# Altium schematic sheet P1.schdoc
size 594 x 419 mm; Symbol: Drawing-Symbol_A4; @Project Name: Inverted_MAML_6x6; @Page Count: 1; @Update Date: 2026-07-20; @Create Date: 2026-07-20; @Schematic Name: Schematic1; @Page No: 1; @Page Name: P1; Company: EasyEDA.com; Version: V1.0; Page Size: A4; Device: Drawing-Symbol_A4; @Create Time: 12:18:09; @Update Time: 12:18:09; Border: 1; Width: 2338; Height: 1652; Region Start: 1; X Region Count: 6; Y Region Count: 4; Blade Width: 10; Title Block Position: 3
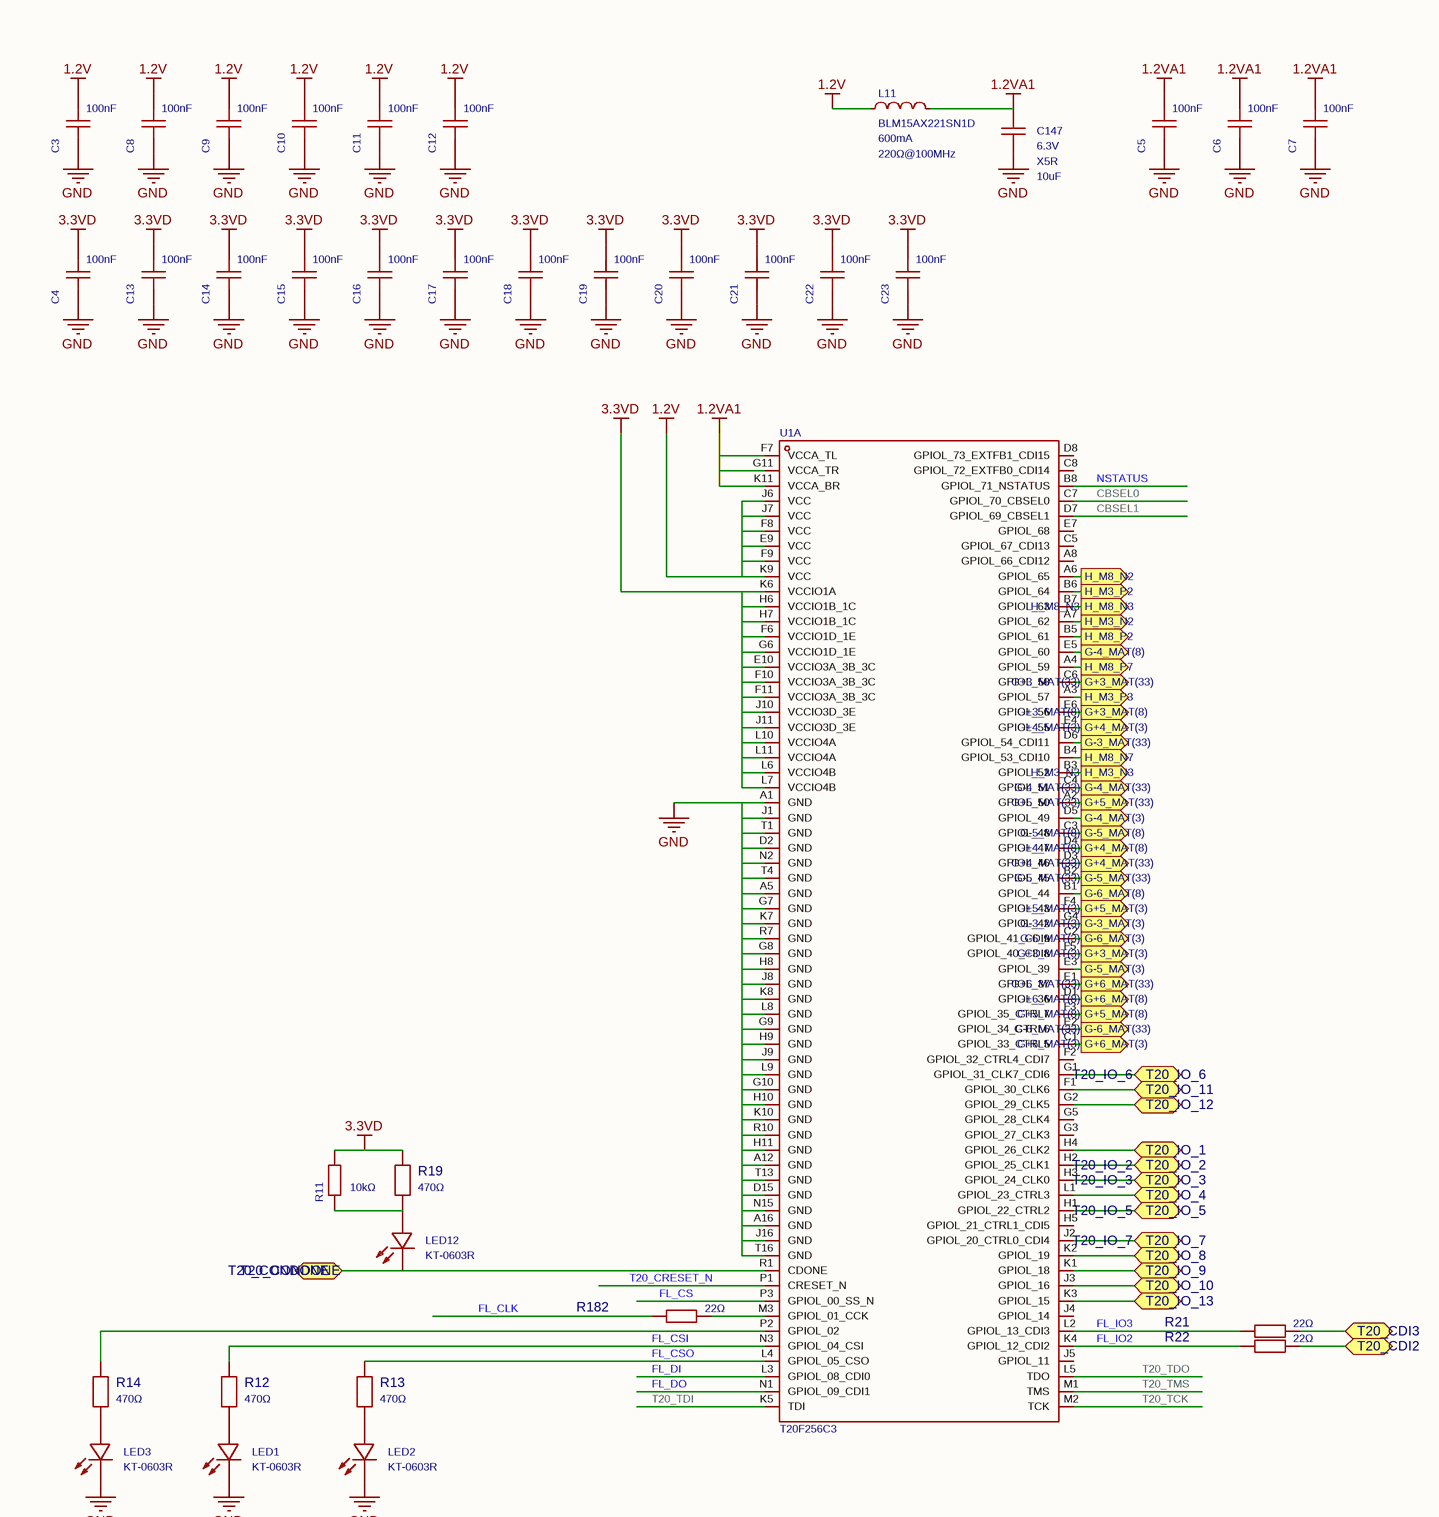
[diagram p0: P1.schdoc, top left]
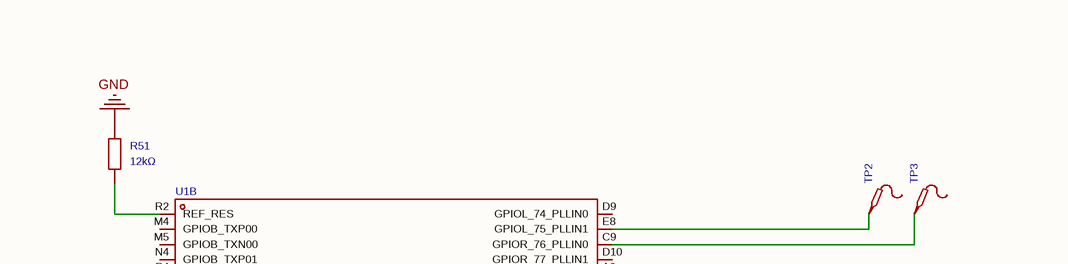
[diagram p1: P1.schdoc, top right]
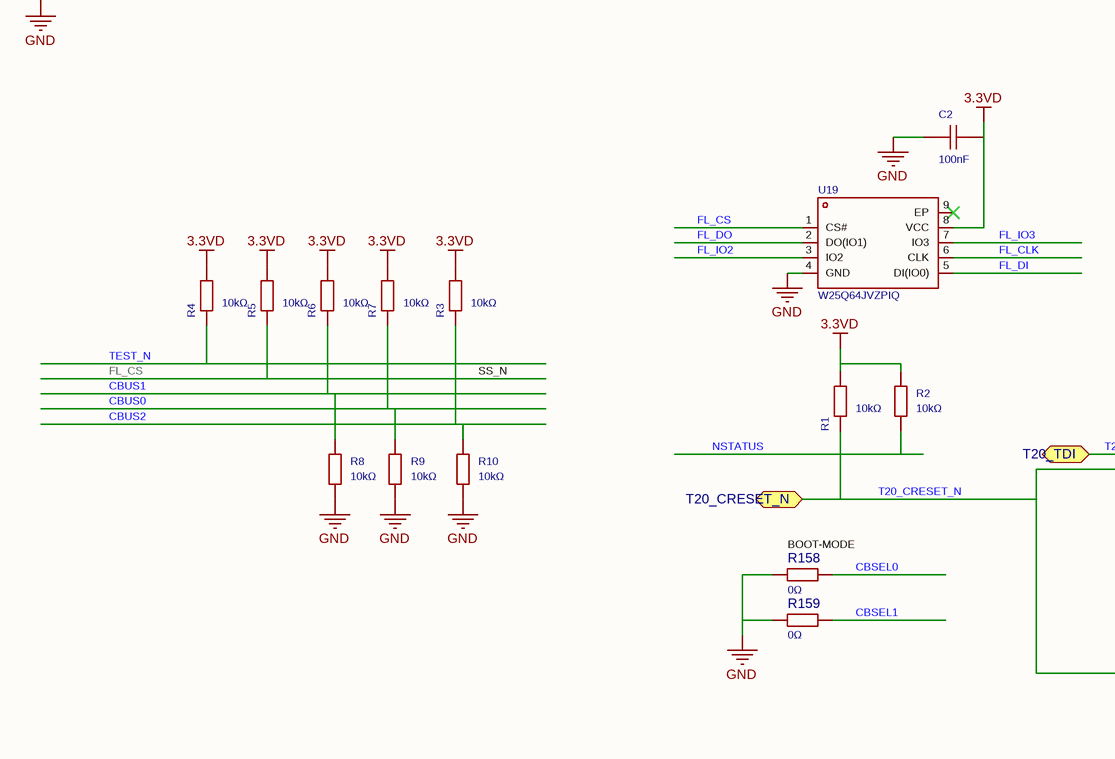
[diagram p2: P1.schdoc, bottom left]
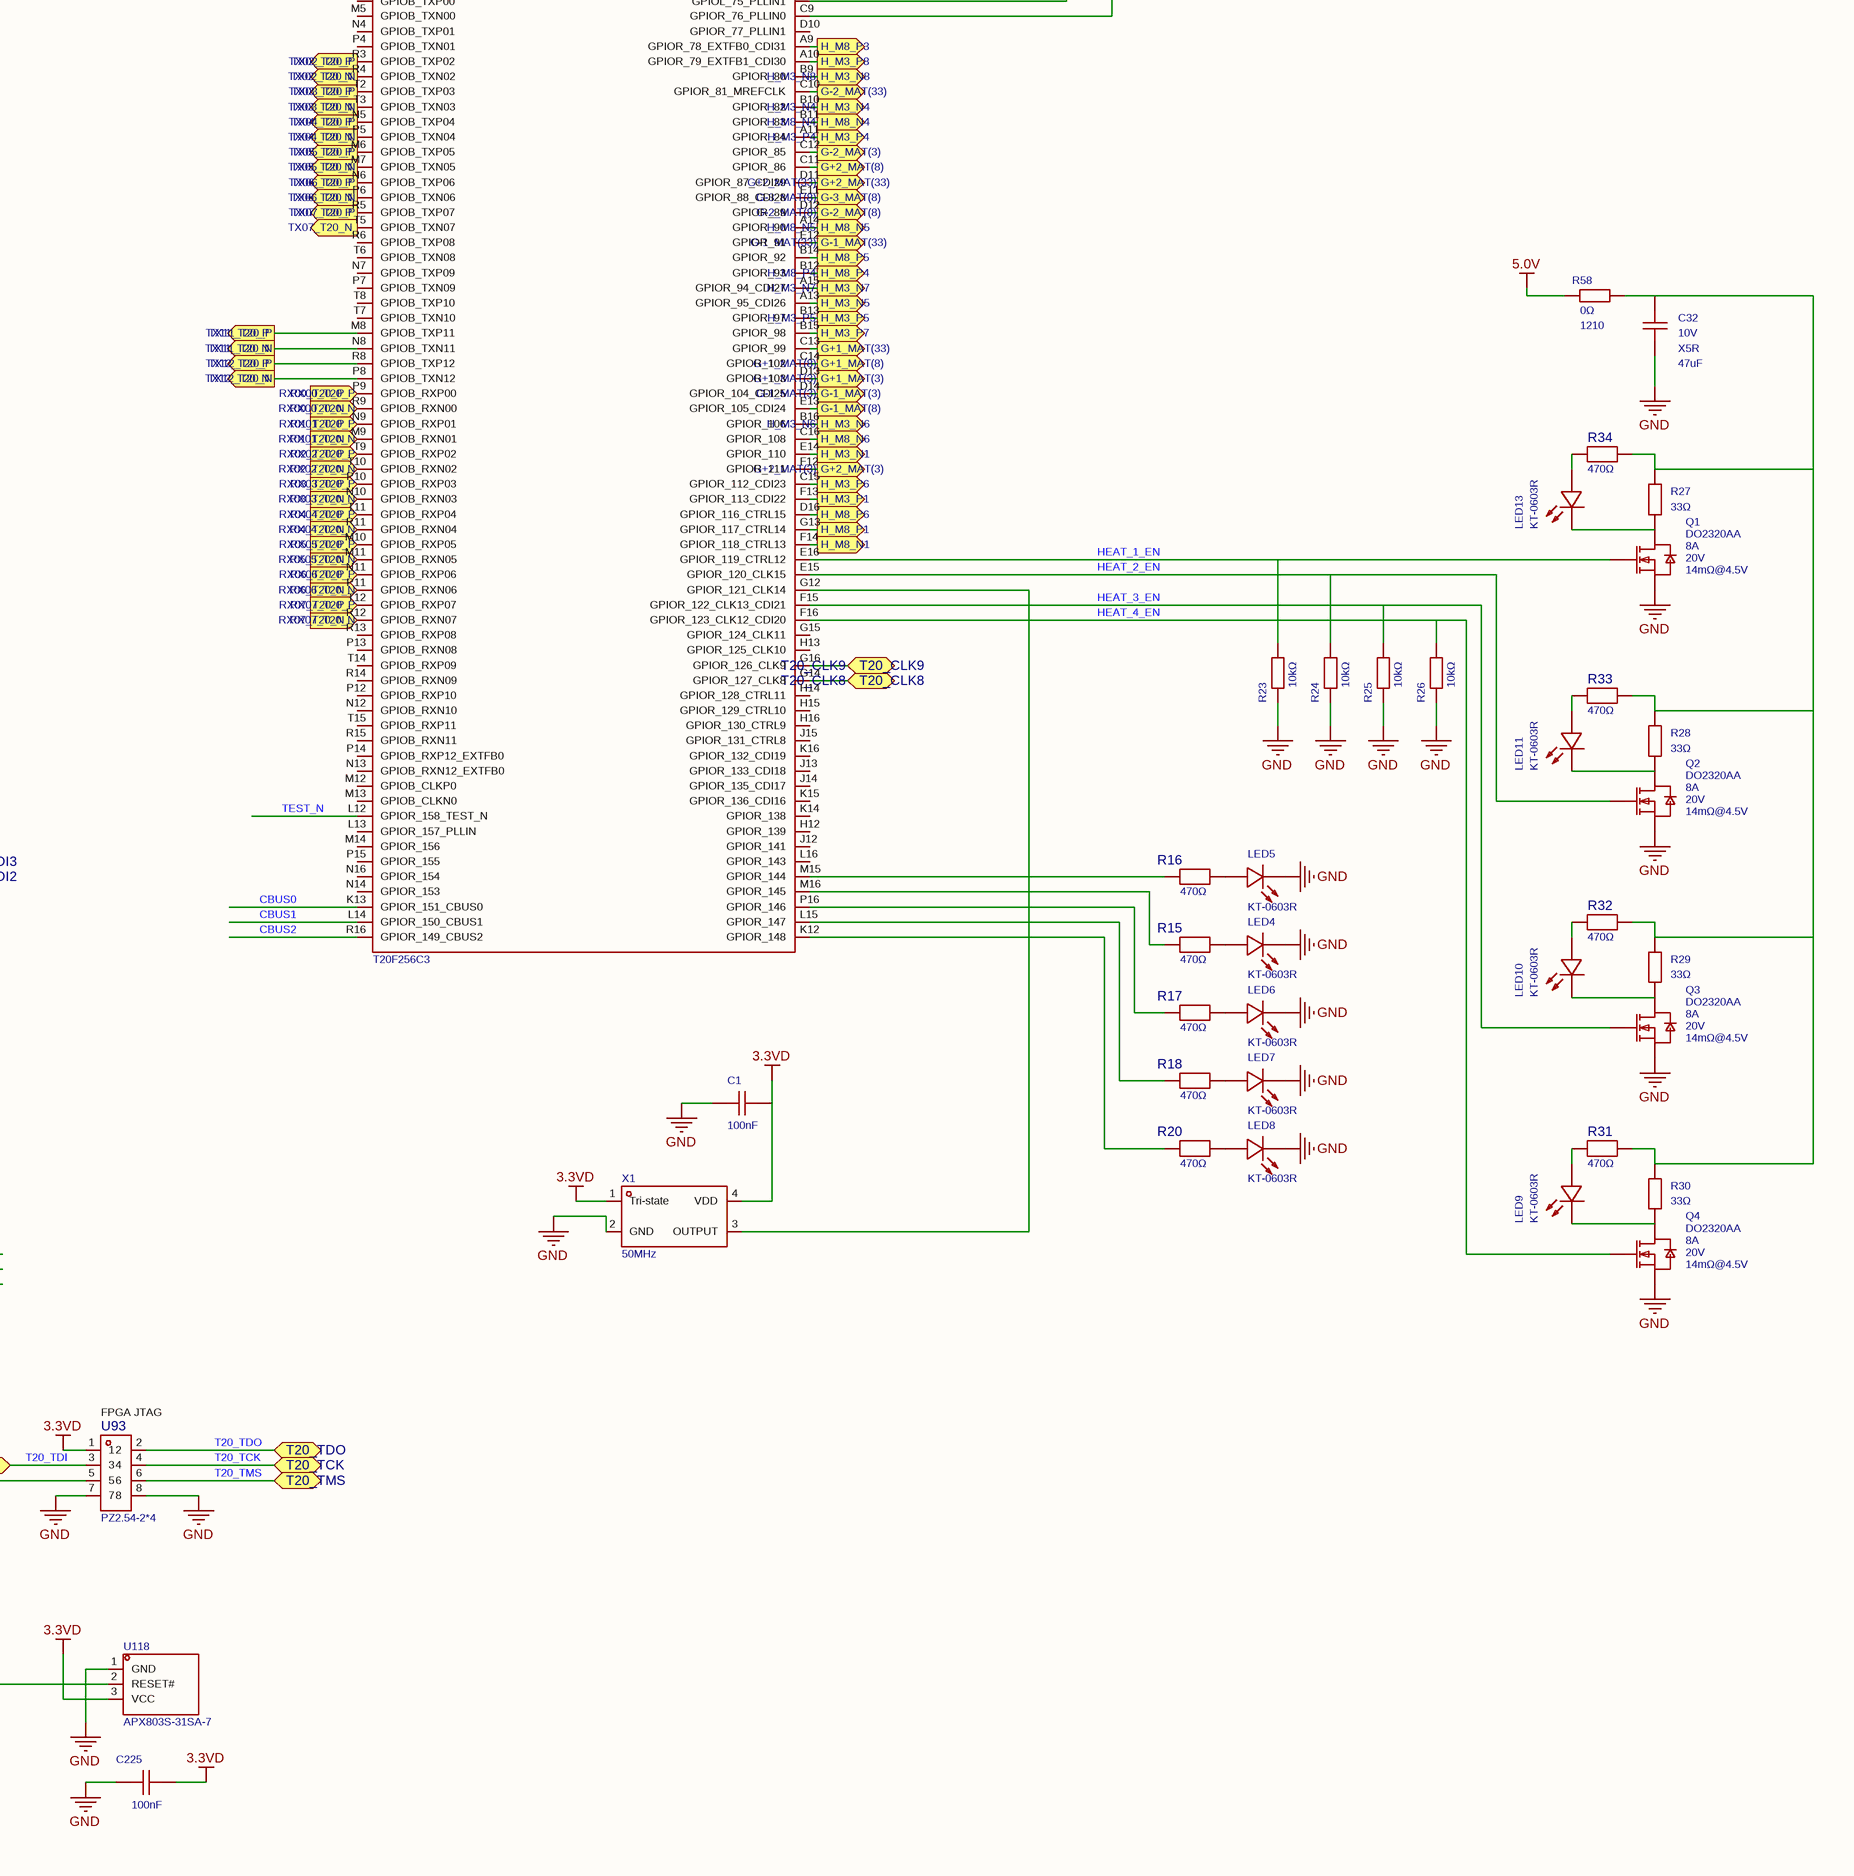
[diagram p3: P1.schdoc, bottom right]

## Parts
C1  100nF  [C0402]
C2  100nF  [C0402]
C3  100nF  [C0201]
C4  100nF  [C0201]
C5  100nF  [C0201]
C6  100nF  [C0201]
C7  100nF  [C0201]
C8  100nF  [C0201]
C9  100nF  [C0201]
C10  100nF  [C0201]
C11  100nF  [C0201]
C12  100nF  [C0201]
C13  100nF  [C0201]
C14  100nF  [C0201]
C15  100nF  [C0201]
C16  100nF  [C0201]
C17  100nF  [C0201]
C18  100nF  [C0201]
C19  100nF  [C0201]
C20  100nF  [C0201]
C21  100nF  [C0201]
C22  100nF  [C0201]
C23  100nF  [C0201]
C32  47uF  Voltage Rating: 10V  Temperature Coefficient: X5R  [C1206]
C147  10uF  Voltage Rating: 6.3V  Temperature Coefficient: X5R  [C0402]
C225  100nF  [C0402]
L11  BLM15AX221SN1D  Impedance @ Frequency: 220Ω@100MHz  Current Rating: 600mA  [L0402]
LED1  KT-0603R  [LED0603-RD]
LED2  KT-0603R  [LED0603-RD]
LED3  KT-0603R  [LED0603-RD]
LED4  KT-0603R  [LED0603-RD]
LED5  KT-0603R  [LED0603-RD]
LED6  KT-0603R  [LED0603-RD]
LED7  KT-0603R  [LED0603-RD]
LED8  KT-0603R  [LED0603-RD]
LED9  KT-0603R  [LED0603-RD]
LED10  KT-0603R  [LED0603-RD]
LED11  KT-0603R  [LED0603-RD]
LED12  KT-0603R  [LED0603-RD]
LED13  KT-0603R  [LED0603-RD]
Q1  DO2320AA  Current - Continuous Drain(Id): 8A  Drain to Source Voltage: 20V  RDS(on): 14mΩ@4.5V  [SOT-23-3_L2.9-W1.6-P1.90-LS2.8-BR]
Q2  DO2320AA  Drain to Source Voltage: 20V  Current - Continuous Drain(Id): 8A  RDS(on): 14mΩ@4.5V  [SOT-23-3_L2.9-W1.6-P1.90-LS2.8-BR]
Q3  DO2320AA  Drain to Source Voltage: 20V  Current - Continuous Drain(Id): 8A  RDS(on): 14mΩ@4.5V  [SOT-23-3_L2.9-W1.6-P1.90-LS2.8-BR]
Q4  DO2320AA  Drain to Source Voltage: 20V  Current - Continuous Drain(Id): 8A  RDS(on): 14mΩ@4.5V  [SOT-23-3_L2.9-W1.6-P1.90-LS2.8-BR]
R1  10kΩ  [R0402]
R2  10kΩ  [R0402]
R3  10kΩ  [R0402]
R4  10kΩ  [R0402]
R5  10kΩ  [R0402]
R6  10kΩ  [R0402]
R7  10kΩ  [R0402]
R8  10kΩ  [R0402]
R9  10kΩ  [R0402]
R10  10kΩ  [R0402]
R11  10kΩ  [R0402]
R12  470Ω  [R0402]
R13  470Ω  [R0402]
R14  470Ω  [R0402]
R15  470Ω  [R0402]
R16  470Ω  [R0402]
R17  470Ω  [R0402]
R18  470Ω  [R0402]
R19  470Ω  [R0402]
R20  470Ω  [R0402]
R21  22Ω  [R0402]
R22  22Ω  [R0402]
R23  10kΩ  [R0402]
R24  10kΩ  [R0402]
R25  10kΩ  [R0402]
R26  10kΩ  [R0402]
R27  33Ω  [R2512]
R28  33Ω  [R2512]
R29  33Ω  [R2512]
R30  33Ω  [R2512]
R31  470Ω  [R0402]
R32  470Ω  [R0402]
R33  470Ω  [R0402]
R34  470Ω  [R0402]
R51  12kΩ  [R0402]
R58  0Ω  Supplier Footprint: 1210  [R1210]
R158  0Ω  [R0402]
R159  0Ω  [R0402]
R182  22Ω  [R0402]
TP2  (no value)  [Test-Point-0.5mm]
TP3  (no value)  [Test-Point-0.5mm]
U1  T20F256C3  [FBGA-256_L13.0-W13.0-R16-C16-P0.80-TL]  (parts A,B of 2)
U19  W25Q64JVZPIQ  [WSON-8_L6.0-W5.0-P1.27-BL-EP]
U93  PZ2.54-2*4  [HDR-TH_8P-P2.54-V-M-R2-C4-S2.54]
U118  APX803S-31SA-7  [SOT-23-3_L2.9-W1.3-P1.90-LS2.4-BR]
X1  50MHz  [OSC-SMD_4P-L3.2-W2.5-BL]

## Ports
G+1_MAT(3) (out), G+1_MAT(8) (out), G+1_MAT(33) (out), G+2_MAT(3) (out), G+2_MAT(8) (out), G+2_MAT(33) (out), G+3_MAT(3) (out), G+3_MAT(8) (out), G+3_MAT(33) (out), G+4_MAT(3) (out), G+4_MAT(8) (out), G+4_MAT(33) (out), G+5_MAT(3) (out), G+5_MAT(8) (out), G+5_MAT(33) (out), G+6_MAT(3) (out), G+6_MAT(8) (out), G+6_MAT(33) (out), G-1_MAT(3) (out), G-1_MAT(8) (out), G-1_MAT(33) (out), G-2_MAT(3) (out), G-2_MAT(8) (out), G-2_MAT(33) (out), G-3_MAT(3) (out), G-3_MAT(8) (out), G-3_MAT(33) (out), G-4_MAT(3) (out), G-4_MAT(8) (out), G-4_MAT(33) (out), G-5_MAT(3) (out), G-5_MAT(8) (out), G-5_MAT(33) (out), G-6_MAT(3) (out), G-6_MAT(8) (out), G-6_MAT(33) (out), H_M3_N1 (out), H_M3_N2 (out), H_M3_N3 (out), H_M3_N4 (out), H_M3_N5 (out), H_M3_N6 (out), H_M3_N7 (out), H_M3_N8 (out), H_M3_P1 (out), H_M3_P2 (out), H_M3_P3 (out), H_M3_P4 (out), H_M3_P5 (out), H_M3_P6 (out), H_M3_P7 (out), H_M3_P8 (out), H_M8_N1 (out), H_M8_N2 (out), H_M8_N3 (out), H_M8_N4 (out), H_M8_N5 (out), H_M8_N6 (out), H_M8_N7 (out), H_M8_P1 (out), H_M8_P2 (out), H_M8_P3 (out), H_M8_P4 (out), H_M8_P5 (out), H_M8_P6 (out), H_M8_P7 (out), RX00_T20_N (in), RX00_T20_P (in), RX01_T20_N (in), RX01_T20_P (in), RX02_T20_N (in), RX02_T20_P (in), RX03_T20_N (in), RX03_T20_P (in), RX04_T20_N (in), RX04_T20_P (in), RX05_T20_N (in), RX05_T20_P (in), RX06_T20_N (in), RX06_T20_P (in), RX07_T20_N (in), RX07_T20_P (in), T20_CDI2 (bidir), T20_CDI3 (bidir), T20_CLK8 (bidir), T20_CLK9 (bidir), T20_CONDONE (bidir), T20_CRESET_N (bidir), T20_IO_1 (bidir), T20_IO_2 (bidir), T20_IO_3 (bidir), T20_IO_4 (bidir), T20_IO_5 (bidir), T20_IO_6 (bidir), T20_IO_7 (bidir), T20_IO_8 (bidir), T20_IO_9 (bidir), T20_IO_10 (bidir), T20_IO_11 (bidir), T20_IO_12 (bidir), T20_IO_13 (bidir), T20_TCK (bidir), T20_TDI (bidir), T20_TDO (bidir), T20_TMS (bidir), TX02_T20_N (out), TX02_T20_P (out), TX03_T20_N (out), TX03_T20_P (out), TX04_T20_N (out), TX04_T20_P (out), TX05_T20_N (out), TX05_T20_P (out), TX06_T20_N (out), TX06_T20_P (out), TX07_T20_N (out), TX07_T20_P (out), TX11_T20_N (out), TX11_T20_P (out), TX12_T20_N (out), TX12_T20_P (out)

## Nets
1.2V: C3.1 C8.1 C9.1 C10.1 C11.1 C12.1 L11.1 U1.E9(VCC) U1.F8(VCC) U1.F9(VCC) U1.J6(VCC) U1.J7(VCC) U1.K9(VCC)
1.2VA1: C5.1 C6.1 C7.1 C147.2 L11.2 U1.F7(VCCA_TL) U1.G11(VCCA_TR) U1.K11(VCCA_BR)
3.3VD: C1.1 C2.1 C4.1 C13.1 C14.1 C15.1 C16.1 C17.1 C18.1 C19.1 C20.1 C21.1 C22.1 C23.1 C225.1 R1.2 R2.2 R3.2 R4.2 R5.2 R6.2 R7.2 R11.2 R19.2 U1.E10(VCCIO3A_3B_3C) U1.F6(VCCIO1D_1E) U1.F10(VCCIO3A_3B_3C) U1.F11(VCCIO3A_3B_3C) U1.G6(VCCIO1D_1E) U1.H6(VCCIO1B_1C) U1.H7(VCCIO1B_1C) U1.J10(VCCIO3D_3E) U1.J11(VCCIO3D_3E) U1.K6(VCCIO1A) U1.L6(VCCIO4B) U1.L7(VCCIO4B) U1.L10(VCCIO4A) U1.L11(VCCIO4A) U19.8(VCC) U93.1 U118.3(VCC) X1.1(Tri-state) X1.4(VDD)
5.0V: R58.1
GND: C1.2 C2.2 C3.2 C4.2 C5.2 C6.2 C7.2 C8.2 C9.2 C10.2 C11.2 C12.2 C13.2 C14.2 C15.2 C16.2 C17.2 C18.2 C19.2 C20.2 C21.2 C22.2 C23.2 C32.1 C147.1 C225.2 LED1.1(K) LED2.1(K) LED3.1(K) LED4.1(K) LED5.1(K) LED6.1(K) LED7.1(K) LED8.1(K) Q1.2(S) Q2.2(S) Q3.2(S) Q4.2(S) R8.1 R9.1 R10.1 R23.1 R24.1 R25.1 R26.1 R51.2 R158.1 R159.1 U1.A1(GND) U1.A5(GND) U1.A12(GND) U1.A16(GND) U1.D2(GND) U1.D15(GND) U1.G7(GND) U1.G8(GND) U1.G9(GND) U1.G10(GND) U1.H8(GND) U1.H9(GND) U1.H10(GND) U1.H11(GND) U1.J1(GND) U1.J8(GND) U1.J9(GND) U1.J16(GND) U1.K7(GND) U1.K8(GND) U1.K10(GND) U1.L8(GND) U1.L9(GND) U1.N2(GND) U1.N15(GND) U1.R7(GND) U1.R10(GND) U1.T1(GND) U1.T4(GND) U1.T13(GND) U1.T16(GND) U19.4(GND) U93.7 U93.8 U118.1(GND) X1.2(GND)
CBSEL0: R158.2 U1.C7(GPIOL_70_CBSEL0)
CBSEL1: R159.2 U1.D7(GPIOL_69_CBSEL1)
CBUS0: R7.1 R9.2 U1.K13(GPIOR_151_CBUS0)
CBUS1: R6.1 R8.2 U1.L14(GPIOR_150_CBUS1)
CBUS2: R3.1 R10.2 U1.R16(GPIOR_149_CBUS2)
FL_CLK: R182.1 U19.6(CLK)
FL_CS: R5.1 U1.P3(GPIOL_00_SS_N) U19.1(CS#)
FL_CSI: R12.2 U1.N3(GPIOL_04_CSI)
FL_CSO: R13.2 U1.L4(GPIOL_05_CSO)
FL_DI: U1.L3(GPIOL_08_CDI0) U19.5(DI(IO0))
FL_DO: U1.N1(GPIOL_09_CDI1) U19.2(DO(IO1))
FL_IO2: R22.1 U1.K4(GPIOL_12_CDI2) U19.3(IO2)
FL_IO3: R21.1 U1.L2(GPIOL_13_CDI3) U19.7(IO3)
G+1_MAT(3): U1.D13(GPIOR_103) ; port G+1_MAT(3)
G+1_MAT(8): U1.C14(GPIOR_102) ; port G+1_MAT(8)
G+1_MAT(33): U1.C13(GPIOR_99) ; port G+1_MAT(33)
G+2_MAT(3): U1.F12(GPIOR_111) ; port G+2_MAT(3)
G+2_MAT(8): U1.C11(GPIOR_86) ; port G+2_MAT(8)
G+2_MAT(33): U1.D11(GPIOR_87_CDI29) ; port G+2_MAT(33)
G+3_MAT(3): U1.F5(GPIOL_40_CDI8) ; port G+3_MAT(3)
G+3_MAT(8): U1.E6(GPIOL_56) ; port G+3_MAT(8)
G+3_MAT(33): U1.C6(GPIOL_58) ; port G+3_MAT(33)
G+4_MAT(3): U1.E4(GPIOL_55) ; port G+4_MAT(3)
G+4_MAT(8): U1.D4(GPIOL_47) ; port G+4_MAT(8)
G+4_MAT(33): U1.D3(GPIOL_46) ; port G+4_MAT(33)
G+5_MAT(3): U1.F4(GPIOL_43) ; port G+5_MAT(3)
G+5_MAT(8): U1.F3(GPIOL_35_CTRL7) ; port G+5_MAT(8)
G+5_MAT(33): U1.A2(GPIOL_50) ; port G+5_MAT(33)
G+6_MAT(3): U1.C1(GPIOL_33_CTRL5) ; port G+6_MAT(3)
G+6_MAT(8): U1.D1(GPIOL_36) ; port G+6_MAT(8)
G+6_MAT(33): U1.E1(GPIOL_37) ; port G+6_MAT(33)
G-1_MAT(3): U1.D14(GPIOR_104_CDI25) ; port G-1_MAT(3)
G-1_MAT(8): U1.E13(GPIOR_105_CDI24) ; port G-1_MAT(8)
G-1_MAT(33): U1.E12(GPIOR_91) ; port G-1_MAT(33)
G-2_MAT(3): U1.C12(GPIOR_85) ; port G-2_MAT(3)
G-2_MAT(8): U1.D12(GPIOR_89) ; port G-2_MAT(8)
G-2_MAT(33): U1.C10(GPIOR_81_MREFCLK) ; port G-2_MAT(33)
G-3_MAT(3): U1.G4(GPIOL_42) ; port G-3_MAT(3)
G-3_MAT(8): U1.E11(GPIOR_88_CDI28) ; port G-3_MAT(8)
G-3_MAT(33): U1.D6(GPIOL_54_CDI11) ; port G-3_MAT(33)
G-4_MAT(3): U1.D5(GPIOL_49) ; port G-4_MAT(3)
G-4_MAT(8): U1.E5(GPIOL_60) ; port G-4_MAT(8)
G-4_MAT(33): U1.C4(GPIOL_51) ; port G-4_MAT(33)
G-5_MAT(3): U1.E3(GPIOL_39) ; port G-5_MAT(3)
G-5_MAT(8): U1.C3(GPIOL_48) ; port G-5_MAT(8)
G-5_MAT(33): U1.B2(GPIOL_45) ; port G-5_MAT(33)
G-6_MAT(3): U1.C2(GPIOL_41_CDI9) ; port G-6_MAT(3)
G-6_MAT(8): U1.B1(GPIOL_44) ; port G-6_MAT(8)
G-6_MAT(33): U1.E2(GPIOL_34_CTRL6) ; port G-6_MAT(33)
H_M3_N1: U1.E14(GPIOR_110) ; port H_M3_N1
H_M3_N2: U1.A7(GPIOL_62) ; port H_M3_N2
H_M3_N3: U1.B3(GPIOL_52) ; port H_M3_N3
H_M3_N4: U1.B10(GPIOR_82) ; port H_M3_N4
H_M3_N5: U1.A13(GPIOR_95_CDI26) ; port H_M3_N5
H_M3_N6: U1.B16(GPIOR_106) ; port H_M3_N6
H_M3_N7: U1.A15(GPIOR_94_CDI27) ; port H_M3_N7
H_M3_N8: U1.B9(GPIOR_80) ; port H_M3_N8
H_M3_P1: U1.F13(GPIOR_113_CDI22) ; port H_M3_P1
H_M3_P2: U1.B6(GPIOL_64) ; port H_M3_P2
H_M3_P3: U1.A3(GPIOL_57) ; port H_M3_P3
H_M3_P4: U1.A11(GPIOR_84) ; port H_M3_P4
H_M3_P5: U1.B13(GPIOR_97) ; port H_M3_P5
H_M3_P6: U1.C15(GPIOR_112_CDI23) ; port H_M3_P6
H_M3_P7: U1.B15(GPIOR_98) ; port H_M3_P7
H_M3_P8: U1.A10(GPIOR_79_EXTFB1_CDI30) ; port H_M3_P8
H_M8_N1: U1.F14(GPIOR_118_CTRL13) ; port H_M8_N1
H_M8_N2: U1.A6(GPIOL_65) ; port H_M8_N2
H_M8_N3: U1.B7(GPIOL_63) ; port H_M8_N3
H_M8_N4: U1.B11(GPIOR_83) ; port H_M8_N4
H_M8_N5: U1.A14(GPIOR_90) ; port H_M8_N5
H_M8_N6: U1.C16(GPIOR_108) ; port H_M8_N6
H_M8_N7: U1.B4(GPIOL_53_CDI10) ; port H_M8_N7
H_M8_P1: U1.G13(GPIOR_117_CTRL14) ; port H_M8_P1
H_M8_P2: U1.B5(GPIOL_61) ; port H_M8_P2
H_M8_P3: U1.A9(GPIOR_78_EXTFB0_CDI31) ; port H_M8_P3
H_M8_P4: U1.B12(GPIOR_93) ; port H_M8_P4
H_M8_P5: U1.B14(GPIOR_92) ; port H_M8_P5
H_M8_P6: U1.D16(GPIOR_116_CTRL15) ; port H_M8_P6
H_M8_P7: U1.A4(GPIOL_59) ; port H_M8_P7
HEAT_1_EN: Q1.1(G) R23.2 U1.E16(GPIOR_119_CTRL12)
HEAT_2_EN: Q2.1(G) R24.2 U1.E15(GPIOR_120_CLK15)
HEAT_3_EN: Q3.1(G) R25.2 U1.F15(GPIOR_122_CLK13_CDI21)
HEAT_4_EN: Q4.1(G) R26.2 U1.F16(GPIOR_123_CLK12_CDI20)
NSTATUS: R2.1 U1.B8(GPIOL_71_NSTATUS)
RX00_T20_N: U1.R9(GPIOB_RXN00) ; port RX00_T20_N
RX00_T20_P: U1.P9(GPIOB_RXP00) ; port RX00_T20_P
RX01_T20_N: U1.M9(GPIOB_RXN01) ; port RX01_T20_N
RX01_T20_P: U1.N9(GPIOB_RXP01) ; port RX01_T20_P
RX02_T20_N: U1.T10(GPIOB_RXN02) ; port RX02_T20_N
RX02_T20_P: U1.T9(GPIOB_RXP02) ; port RX02_T20_P
RX03_T20_N: U1.N10(GPIOB_RXN03) ; port RX03_T20_N
RX03_T20_P: U1.P10(GPIOB_RXP03) ; port RX03_T20_P
RX04_T20_N: U1.R11(GPIOB_RXN04) ; port RX04_T20_N
RX04_T20_P: U1.T11(GPIOB_RXP04) ; port RX04_T20_P
RX05_T20_N: U1.M11(GPIOB_RXN05) ; port RX05_T20_N
RX05_T20_P: U1.M10(GPIOB_RXP05) ; port RX05_T20_P
RX06_T20_N: U1.P11(GPIOB_RXN06) ; port RX06_T20_N
RX06_T20_P: U1.N11(GPIOB_RXP06) ; port RX06_T20_P
RX07_T20_N: U1.R12(GPIOB_RXN07) ; port RX07_T20_N
RX07_T20_P: U1.T12(GPIOB_RXP07) ; port RX07_T20_P
T20_CDI2: R22.2 ; port T20_CDI2
T20_CDI3: R21.2 ; port T20_CDI3
T20_CLK8: U1.G14(GPIOR_127_CLK8) ; port T20_CLK8
T20_CLK9: U1.G16(GPIOR_126_CLK9) ; port T20_CLK9
T20_CONDONE: LED12.1(K) U1.R1(CDONE) ; port T20_CONDONE
T20_CRESET_N: R1.1 U1.P1(CRESET_N) U93.5 U118.2(RESET#) ; port T20_CRESET_N
T20_IO_1: U1.H4(GPIOL_26_CLK2) ; port T20_IO_1
T20_IO_2: U1.H2(GPIOL_25_CLK1) ; port T20_IO_2
T20_IO_3: U1.H3(GPIOL_24_CLK0) ; port T20_IO_3
T20_IO_4: U1.L1(GPIOL_23_CTRL3) ; port T20_IO_4
T20_IO_5: U1.H1(GPIOL_22_CTRL2) ; port T20_IO_5
T20_IO_6: U1.G1(GPIOL_31_CLK7_CDI6) ; port T20_IO_6
T20_IO_7: U1.J2(GPIOL_20_CTRL0_CDI4) ; port T20_IO_7
T20_IO_8: U1.K2(GPIOL_19) ; port T20_IO_8
T20_IO_9: U1.K1(GPIOL_18) ; port T20_IO_9
T20_IO_10: U1.J3(GPIOL_16) ; port T20_IO_10
T20_IO_11: U1.F1(GPIOL_30_CLK6) ; port T20_IO_11
T20_IO_12: U1.G2(GPIOL_29_CLK5) ; port T20_IO_12
T20_IO_13: U1.K3(GPIOL_15) ; port T20_IO_13
T20_TCK: U1.M2(TCK) U93.4 ; port T20_TCK
T20_TDI: U1.K5(TDI) U93.3 ; port T20_TDI
T20_TDO: U1.L5(TDO) U93.2 ; port T20_TDO
T20_TMS: U1.M1(TMS) U93.6 ; port T20_TMS
TEST_N: R4.1 U1.L12(GPIOR_158_TEST_N)
TX02_T20_N: U1.R4(GPIOB_TXN02) ; port TX02_T20_N
TX02_T20_P: U1.R3(GPIOB_TXP02) ; port TX02_T20_P
TX03_T20_N: U1.T3(GPIOB_TXN03) ; port TX03_T20_N
TX03_T20_P: U1.T2(GPIOB_TXP03) ; port TX03_T20_P
TX04_T20_N: U1.P5(GPIOB_TXN04) ; port TX04_T20_N
TX04_T20_P: U1.N5(GPIOB_TXP04) ; port TX04_T20_P
TX05_T20_N: U1.M7(GPIOB_TXN05) ; port TX05_T20_N
TX05_T20_P: U1.M6(GPIOB_TXP05) ; port TX05_T20_P
TX06_T20_N: U1.P6(GPIOB_TXN06) ; port TX06_T20_N
TX06_T20_P: U1.N6(GPIOB_TXP06) ; port TX06_T20_P
TX07_T20_N: U1.T5(GPIOB_TXN07) ; port TX07_T20_N
TX07_T20_P: U1.R5(GPIOB_TXP07) ; port TX07_T20_P
TX11_T20_N: U1.N8(GPIOB_TXN11) ; port TX11_T20_N
TX11_T20_P: U1.M8(GPIOB_TXP11) ; port TX11_T20_P
TX12_T20_N: U1.P8(GPIOB_TXN12) ; port TX12_T20_N
TX12_T20_P: U1.R8(GPIOB_TXP12) ; port TX12_T20_P
NetC32_2: C32.2 R27.2 R28.2 R29.2 R30.2 R31.1 R32.1 R33.1 R34.1 R58.2
NetLED1_2: LED1.2(A) R12.1
NetLED2_2: LED2.2(A) R13.1
NetLED3_2: LED3.2(A) R14.1
NetLED4_2: LED4.2(A) R15.1
NetLED5_2: LED5.2(A) R16.1
NetLED6_2: LED6.2(A) R17.1
NetLED7_2: LED7.2(A) R18.1
NetLED8_2: LED8.2(A) R20.1
NetLED9_1: LED9.1(K) Q4.3(D) R30.1
NetLED9_2: LED9.2(A) R31.2
NetLED10_1: LED10.1(K) Q3.3(D) R29.1
NetLED10_2: LED10.2(A) R32.2
NetLED11_1: LED11.1(K) Q2.3(D) R28.1
NetLED11_2: LED11.2(A) R33.2
NetLED12_2: LED12.2(A) R11.1 R19.1
NetLED13_1: LED13.1(K) Q1.3(D) R27.1
NetLED13_2: LED13.2(A) R34.2
NetR14_2: R14.2 U1.P2(GPIOL_02)
NetR15_2: R15.2 U1.M16(GPIOR_145)
NetR16_2: R16.2 U1.M15(GPIOR_144)
NetR17_2: R17.2 U1.P16(GPIOR_146)
NetR18_2: R18.2 U1.L15(GPIOR_147)
NetR20_2: R20.2 U1.K12(GPIOR_148)
NetR51_1: R51.1 U1.R2(REF_RES)
NetR182_2: R182.2 U1.M3(GPIOL_01_CCK)
NetTP2_1: TP2.1 U1.E8(GPIOL_75_PLLIN1)
NetTP3_1: TP3.1 U1.C9(GPIOR_76_PLLIN0)
NetU1_G12: U1.G12(GPIOR_121_CLK14) X1.3(OUTPUT)

Not connected (* = marked no-connect by the designer): U1 A8(GPIOL_66_CDI12) C5(GPIOL_67_CDI13) C8(GPIOL_72_EXTFB0_CDI14) D8(GPIOL_73_EXTFB1_CDI15) D9(GPIOL_74_PLLIN0) D10(GPIOR_77_PLLIN1) E7(GPIOL_68) F2(GPIOL_32_CTRL4_CDI7) G3(GPIOL_27_CLK3) G5(GPIOL_28_CLK4) G15(GPIOR_124_CLK11) H5(GPIOL_21_CTRL1_CDI5) H12(GPIOR_139) H13(GPIOR_125_CLK10) H14(GPIOR_128_CTRL11) H15(GPIOR_129_CTRL10) H16(GPIOR_130_CTRL9) J4(GPIOL_14) J5(GPIOL_11) J12(GPIOR_141) J13(GPIOR_133_CDI18) J14(GPIOR_135_CDI17) J15(GPIOR_131_CTRL8) K14(GPIOR_138) K15(GPIOR_136_CDI16) K16(GPIOR_132_CDI19) L13(GPIOR_157_PLLIN) L16(GPIOR_143) M4(GPIOB_TXP00) M5(GPIOB_TXN00) M12(GPIOB_CLKP0) M13(GPIOB_CLKN0) M14(GPIOR_156) N4(GPIOB_TXP01) N7(GPIOB_TXP09) N12(GPIOB_RXN10) N13(GPIOB_RXN12_EXTFB0) N14(GPIOR_153) N16(GPIOR_154) P4(GPIOB_TXN01) P7(GPIOB_TXN09) P12(GPIOB_RXP10) P13(GPIOB_RXN08) P14(GPIOB_RXP12_EXTFB0) P15(GPIOR_155) R6(GPIOB_TXP08) R13(GPIOB_RXP08) R14(GPIOB_RXN09) R15(GPIOB_RXN11) T6(GPIOB_TXN08) T7(GPIOB_TXN10) T8(GPIOB_TXP10) T14(GPIOB_RXP09) T15(GPIOB_RXP11); U19 9(EP)*

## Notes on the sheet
- SS_N
- (near U93) FPGA JTAG
- (near R158) BOOT-MODE

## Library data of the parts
C1 C2 C225 = CL05B104KB54PNC: Capacitance: Tolerance:±10% Tolerance:±10% Voltage Rated: Temperature Coefficient:; Manufacturer: SAMSUNG(三星); Check: true; 3D Model: b7d13df3e9464d7a99d0651d1a5b4d57; 3D Model Transform: 39.37,19.685,0,0,0,0,0,0,0; Tolerance: ±10%; AddInBom: yes; ModelName: C0402_L1.0-W0.5-H0.5
C3-C23 = CL03A104KP3NNNC: Capacitance:100nF Tolerance:±10% Tolerance:±10% Voltage Rating:10V Temperature Coefficient:X5R; Manufacturer: SAMSUNG(三星); Add into BOM: yes; 3D Model: c3e75c3d90204c70b153866ab54c789f; 3D Model Transform: 23.622,11.811,0,0,0,0,0,0,0; Tolerance: ±10%; Temperature Coefficient: X5R; Voltage Rating: 10V; ModelName: C0201_L0.6-W0.3-H0.3
C32 = CL31A476MPHNNNE: Capacitance:47uF Tolerance:±20% Tolerance:±20% Voltage Rating:10V Temperature Coefficient:X5R; Manufacturer: SAMSUNG(三星); 3D Model: c6790e9475e1483991d2c64340b24e96; 3D Model Transform: 125.984,62.992,0,0,0,0,0,0,0; Tolerance: ±20%; AddInBom: yes; ModelName: C1206_L3.2-W1.6-H1.3
C147 = CL05A106MQ5NUNC: Capacitance:10uF Tolerance:±20% Tolerance:±20% Voltage Rating:6.3V Temperature Coefficient:X5R; Manufacturer: SAMSUNG(三星); 3D Model: b7d13df3e9464d7a99d0651d1a5b4d57; 3D Model Transform: 39.37,19.685,0,0,0,0,0,0,0; Tolerance: ±20%; AddInBom: yes; ModelName: C0402_L1.0-W0.5-H0.5
L11 = BLM15AX221SN1D: Impedance @ Frequency:220Ω@100MHz Tolerance:±25% Tolerance:±25% DC Resistance(DCR):180mΩ Current Rating:600mA Number of Circuits:1 Operating Temperature:-55℃~+125℃ Operating Temperature:-55℃~+125℃; Manufacturer: muRata(村田); 3D Model: aef00b1603224fd68a96e37121ccc916; 3D Model Transform: 39.37,19.685,0,0,0,0,0,0.0005,0; Tolerance: ±25%; DC Resistance(DCR): 180mΩ; Number of Circuits: 1; AddInBom: yes; ModelName: L0402_L1.0-W0.5-H0.5_BEAD
LED1-LED13 = KT-0603R: Emitted Color:Red Power Dissipation:- Forward Current:- Dominant Wavelength:- Dominant Wavelength:- Peak Wavelength:- Diode Configuration:- Lens Color:- Color Temperature:- Color Temperature:- Viewing Angle:- Mounting Sytle:- Operating Temperature:-40℃~+8; Manufacturer: KENTO; 3D Model: 5e3b568068dd46cf8019c1d1baa0031b; 3D Model Transform: 63.7794,32.283,0,0,0,0,0,0,0; Emitted Color: Red; AddInBom: yes
Q1-Q4 = DO2320AA: Drain to Source Voltage:20V Current - Continuous Drain(Id):8A RDS(on):14mΩ@4.5V Pd - Power Dissipation:1.5W Gate Threshold Voltage (Vgs(th)):1.2V@250uA Gate Charge(Qg):15nC@4.5V Input Capacitance(Ciss):950pF@10V Reverse Transfer Capacitance (Crss@Vds):155; Manufacturer: DOINGTER(杜因特); AddInBom: yes; ModelId: 4eed685bb9f4439b846746bc2193f3c00819f05c4eef4c71ace90d822a990e87; ModelName: SOT-23-3L_L2.9-W1.6-H1.1-LS2.8-P0.95; ModelTransform: 114.173,110.236,0,90,0,0,0,0,0; Pd - Power Dissipation: 1.5W; Reverse Transfer Capacitance (Crss@Vds): 155pF@10V; Type: N-Channel; Output Capacitance(Coss): 175pF
R1-R7 R11 R23-R26 = 0402WGF1002TCE: Type:Thick Film Resistors Resistance:10kΩ Tolerance:±1% Tolerance:±1% Power(Watts): Overload Voltage (Max): Temperature Coefficient:±100ppm/℃ Temperature Coefficient:±100ppm/℃ Operating Temperature Range:-55℃~+155℃ Operating Temperature Range:-55℃~+155℃; Manufacturer: UNI-ROYAL(厚声); 3D Model: efdecb7dae4442949d28eecaf748420f; 3D Model Transform: 39.37,19.685,0,0,0,0,0,0,0; Tolerance: ±1%; AddInBom: yes; ModelName: R0402_L1.0-W0.5-H0.4
R8-R10 = 0402WGF1002TCE: Type:Thick Film Resistors Resistance:10kΩ Tolerance:±1% Tolerance:±1% Power(Watts): Overload Voltage (Max): Temperature Coefficient:±100ppm/℃ Temperature Coefficient:±100ppm/℃ Operating Temperature Range:-55℃~+155℃ Operating Temperature Range:-55℃~+155℃; Manufacturer: UNI-ROYAL(厚声); Add into BOM: no; 3D Model: efdecb7dae4442949d28eecaf748420f; 3D Model Transform: 39.37,19.685,0,0,0,0,0,0,0; Tolerance: ±1%; ConvertToPcb: yes; ModelName: R0402_L1.0-W0.5-H0.4
R12-R20 R31-R34 = 0402WGF4700TCE: Type:Thick Film Resistors Resistance: Tolerance:±1% Tolerance:±1% Power(Watts): Overload Voltage (Max): Temperature Coefficient:±100ppm/℃ Temperature Coefficient:±100ppm/℃ Operating Temperature Range:-55℃~+155℃ Operating Temperature Range:-55℃~+155℃; Manufacturer: UNI-ROYAL(厚声); Symbol: ERJ2RKF4700X; 3D Model: efdecb7dae4442949d28eecaf748420f; 3D Model Transform: 39.37,19.685,0,0,0,0,0,0,0; Tolerance: ±1%; AddInBom: yes; ModelName: R0402_L1.0-W0.5-H0.4
R21 R22 R182 = 0402WGF220JTCE: Type:Thick Film Resistors Resistance:22Ω Tolerance:±1% Tolerance:±1% Power(Watts): Overload Voltage (Max): Temperature Coefficient:±100ppm/℃ Temperature Coefficient:±100ppm/℃ Operating Temperature Range:-55℃~+155℃ Operating Temperature Range:-55℃~+155℃; Manufacturer: UNI-ROYAL(厚声); 3D Model: efdecb7dae4442949d28eecaf748420f; 3D Model Transform: 39.37,19.685,0,0,0,0,0,0,0; Tolerance: ±1%; AddInBom: yes; ModelName: R0402_L1.0-W0.5-H0.4
R27-R30 = CRH2512F33R0E04Z: Type:Thick Film Resistor Resistance:33Ω Tolerance:±1% Tolerance:±1% Power(Watts):2W Voltage-Supply(Max):200V Temperature Coefficient:±100ppm/℃ Temperature Coefficient:±100ppm/℃ Operating Temperature:-55℃~+155℃ Operating Temperature:-55℃~+155℃; Manufacturer: EVER OHMS(天二科技); Symbol: CR2512F33RE042W; AddInBom: yes; ModelId: c704f12ea0da45b6b9e7d0ddac98e7f70819f05c4eef4c71ace90d822a990e87; ModelName: R2512_L6.3-W3.2-H0.6; ModelTransform: 248.031,125.984,0,0,0,0,-0.0005,0,0; Tolerance: ±1%; Power(Watts): 2W; Voltage-Supply(Max): 200V
R51 = 0402WGF1202TCE: Type:Thick Film Resistor Resistance:12kΩ Tolerance:±1% Tolerance:±1% Power(Watts):62.5mW Voltage-Supply(Max):50V Temperature Coefficient:±100ppm/℃ Temperature Coefficient:±100ppm/℃ Operating Temperature:-55℃~+155℃ Operating Temperature:-55℃~+155℃; Manufacturer: UNI-ROYAL(厚声); 3D Model: efdecb7dae4442949d28eecaf748420f0819f05c4eef4c71ace90d822a990e87; 3D Model Transform: 39.37,19.685,0,0,0,0,0,0,0; Tolerance: ±1%; Power(Watts): 62.5mW; Voltage-Supply(Max): 50V; AddInBom: yes; ModelName: R0402_L1.0-W0.5-H0.4
R58 = RS-1210000JT: Type:Thick Film Resistors Resistance:0Ω Tolerance:±5% Tolerance:±5% Power(Watts):1/3W Voltage-Supply(Max):200V Operating Temperature:-55℃~+155℃ Operating Temperature:-55℃~+155℃; Manufacturer: FH(风华); 3D Model: 20ff733cacdd4b0e91bc367113f3d8ae; 3D Model Transform: 125.984,102.362,0,0,0,0,0,0,0; Tolerance: ±5%; Power(Watts): 1/3W; Voltage-Supply(Max): 200V; AddInBom: yes; ModelName: R1210_L3.2-W2.6-H0.6
R158 R159 = 0402WGF0000TCE: Type:Thick Film Resistor Resistance:0Ω Tolerance:±1% Tolerance:±1% Power(Watts):62.5mW Voltage-Supply(Max):50V Temperature Coefficient:±800ppm/℃ Temperature Coefficient:±800ppm/℃ Operating Temperature:-55℃~+155℃ Operating Temperature:-55℃~+155℃; Manufacturer: UNI-ROYAL(厚声); 3D Model: efdecb7dae4442949d28eecaf748420f; 3D Model Transform: 39.37,19.685,0,0,0,0,0,0,0; Tolerance: ±1%; Power(Watts): 62.5mW; Voltage-Supply(Max): 50V; AddInBom: yes; ModelName: R0402_L1.0-W0.5-H0.4
TP2 TP3 = Test-Point: Test Point 测试点; AddInBom: yes
U1 = T20F256C3: Type:- Voltage - Supply(VCCIO):- Voltage - Supply(VCCIO):- Number of Logic Elements/Blocks:19728 Logic Array Blocks:- Embedded Block RAM:1069548bit Operating Temperature:0℃~+85℃ Operating Temperature:0℃~+85℃; Manufacturer: Efinix; Relevance: []; 3D Model: e2cc585e70ec454792aa60ed0f9ac0c735c85bb2db714cc0b6b9bd1de0d8cd0c; 3D Model Transform: 511.81,511.81,0,0,0,0,0,0,0; Number of Logic Elements/Blocks: 19728; AddInBom: yes
U19 = W25Q64JVZPIQ: Interface Type:SPI Memory Size:64Mbit Clock Frequency (fc):133MHz Supply Voltage:2.7V~3.6V Supply Voltage:2.7V~3.6V Page Programming Time (Tpp):400us Block Erase Time (tBE):120ms@(32KB) Data Retention - TDR (Year):20 years Operating Temperature:-40℃~+85℃; Manufacturer: WINBOND(华邦); Check: true; 3D Model: dfb5b18473104f55ab3029446c4cfe60; 3D Model Transform: 237.007,196.85,0,90,0,0,0,0,0; Interface Type: SPI; Memory Size: 64Mbit; Clock Frequency (fc): 133MHz; Page Programming Time (Tpp): 400us; AddInBom: yes; ModelName: WSON-8_L6.0-W5.0-H0.7-P1.27
U93 = PZ2.54-2*4: Pin Structure:2x4P Pitch:2.54mm Number of Rows:双排 Number of Pins:8P; Manufacturer: ZHOURI(洲日); Check: true; 3D Model: 47b5ce995b664298ab05f1b74b77106f; 3D Model Transform: 399.999,200,0,0,0,0,0,0,-118.11; Pin Structure: 2x4P; Pitch: 2.54mm; AddInBom: yes; ModelName: HDR-TH_8P-P2.54-M-LI-2X4P
U118 = APX803S-31SA-7: ChipType:Voltage Monitor Output Type:Open Drain Voltage - Supply:1V~5.5V Voltage - Supply:1V~5.5V Reset Active Level:Active Low Threshold Voltage:3.08V Number of Voltages Monitored:1 Manual Reset:No Watchdog:No Reset Timeout:240ms Operating Temperature:-4; Manufacturer: DIODES(美台); 3D Model: 62a57c6760504a01965db6419a6d07df; 3D Model Transform: 98.425,114.173,0,180,0,0,0.0005,-0.0005,0; Threshold Voltage: 3.08V; Number of Voltages Monitored: 1; Manual Reset: No; Reset Timeout: 240ms; AddInBom: yes; ModelName: SOT-23-3P_L2.9-W1.3-H1.0-LS2.4-P0.95
X1 = OT322550MJBA4SL: Frequency:50MHz Normal temperature Frequency Tolerance:±10ppm Normal temperature Frequency Tolerance:±10ppm Output Type:CMOS Voltage - Supply:1.8V~3.3V Voltage - Supply:1.8V~3.3V Frequency Stability:±20ppm Frequency Stability:±20ppm Operating Temperature:; Manufacturer: YXC(扬兴晶振); 3D Model: 3d8e5f33629249f9a4089449c02742d4; 3D Model Transform: 125.984,98.425,0,0,0,0,0,0,0; Normal temperature Frequency Tolerance: ±10ppm; Output Type: CMOS; Frequency Stability: ±20ppm; AddInBom: yes; ModelName: OSC-SMD_4P-L3.2-W2.5-H1.0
